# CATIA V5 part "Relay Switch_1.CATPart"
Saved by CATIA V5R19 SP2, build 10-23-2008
Part number: Relay Switch_1
Definition: Relay Switch
Nomenclature: Relay Switch v6
Source: Unknown
Bounding box of the stored display mesh (mm): x 0 to 50, y 0 to 16.43, z 0 to 26
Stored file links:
  Z:\fausse table rondelle-20220905T211342Z-001\fausse table rondelle\Relay Switch_1.CATPart
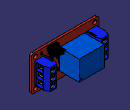
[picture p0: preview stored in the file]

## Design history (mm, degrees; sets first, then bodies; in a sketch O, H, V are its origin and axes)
AxisSystem1: origin (0, 0, 0), X (1, 0, 0), Y (0, 1, 0), Z (0, 0, 1)
Body1 "Bodemplaatje" (main body)
  Solid1: solid without history
Body2 "Pinblokje"
  Solid2: solid without history
Body3 "Processor"
  Solid3: solid without history
Body4 "Connector Rechts"
  Solid4: solid without history
Body5 "Connector Links"
  Solid5: solid without history
Body6 "Flipflop"
  Solid6: solid without history
Body7 "Pin1"
  Solid7: solid without history
Body8 "Dipswitch"
  Solid8: solid without history
Body9 "Pin2"
  Solid9: solid without history
Body10 "Pin3"
  Solid10: solid without history
Body11 "Pinconnector"
  Solid11: solid without history
Body12 "Body19"
  Solid12: solid without history
Body13 "Body20"
  Solid13: solid without history
Body14 "Body21"
  Solid14: solid without history
Body15 "Body22"
  Solid15: solid without history
Body16 "Body23"
  Solid16: solid without history
Body17 "Body24"
  Solid17: solid without history
Body18 "Body25"
  Solid18: solid without history
Body19 "Body26"
  Solid19: solid without history
Body20 "Body27"
  Solid20: solid without history
Body21 "Body28"
  Solid21: solid without history
Body22 "Body29"
  Solid22: solid without history
Body23 "Body30"
  Solid23: solid without history
Body24 "Body31"
  Solid24: solid without history
Body25 "Body32"
  Solid25: solid without history
Body26 "Body33"
  Solid26: solid without history
Body27 "Body34"
  Solid27: solid without history
Body28 "Body35"
  Solid28: solid without history
Body29 "Body36"
  Solid29: solid without history
Body30 "Body37"
  Solid30: solid without history
Body31 "Body38"
  Solid31: solid without history
Body32 "Body39"
  Solid32: solid without history
Body33 "Body40"
  Solid33: solid without history
Body34 "Body41"
  Solid34: solid without history
Body35 "Body42"
  Solid35: solid without history
Body36 "Body43"
  Solid36: solid without history
Body37 "Body44"
  Solid37: solid without history
Body38 "Chip"
  Solid38: solid without history
Body39 "LED1"
  Solid39: solid without history
Body40 "LED2"
  Solid40: solid without history
Body41 "Body48"
  Solid41: solid without history
Body42 "Body49"
  Solid42: solid without history
Body43 "Body50"
  Solid43: solid without history
Body44 "Body51"
  Solid44: solid without history
Body45 "Body52"
  Solid45: solid without history
Body46 "Body53"
  Solid46: solid without history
